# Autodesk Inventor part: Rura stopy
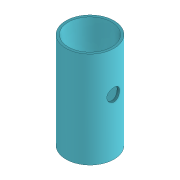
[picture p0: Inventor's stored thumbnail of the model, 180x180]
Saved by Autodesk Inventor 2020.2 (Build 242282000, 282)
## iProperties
Created: 2011-11
Part Number: Rura stopy
Material: Stal
Document SubType Name: Modeling
Designer: F.Stasiak
Density: 7.85 g/cm^3
Mass: 496.498 g
Surface Area: 435.781 cm^2
Volume: 63.2481 cm^3
Appearance: Niebieska z odcieniem szarości
Catalog Web Link: www.expertbooks.pl
Manager: www.cadconsulting.pl
Company: Fabian Stasiak CAD Consulting
Author: F.Stasiak
Subject: Zbiór ćwiczeń. Autodesk Inventor 2020. Kurs Professional
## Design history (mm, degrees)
sketch "Szkic1"
  geometry: C1 r 30 at (0, 0); C2 r 27 at (0, 0); 1 further point
  constraints: 2 centre point, 2 coincident
  dimensions: "GRUBOŚĆ_RURY_STOPY" = 3 radial gap between concentric circles of C1 C2; "d10" = 54 diameter of C2
extrude "Wyciągnięcie proste1" new body sketch "Szkic1" distance "d2" = 120; taper "d3" = 0 deg
sketch "Szkic2"
  geometry: C1 r 8 at (0, 70); 1 further point
  constraints: 1 centre point, 1 vertical alignment
  dimensions: "d4" = 16 diameter of C1; "d5" = 70 distance of point (0, 0) C1.centre
extrude "Wyciągnięcie proste2" cut sketch "Szkic2" extent not by distance; stored distance "d6" = 120; taper "d7" = 0 deg
node "Bryła1"
